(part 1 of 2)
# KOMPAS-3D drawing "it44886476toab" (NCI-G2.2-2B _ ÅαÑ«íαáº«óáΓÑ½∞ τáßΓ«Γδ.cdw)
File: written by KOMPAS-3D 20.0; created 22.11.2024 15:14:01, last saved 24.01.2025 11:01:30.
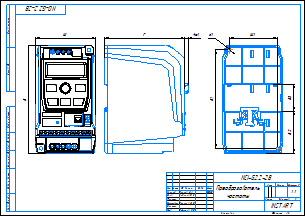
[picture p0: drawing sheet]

Sheet 1: A3, landscape

Document properties: Автор: admin; Полное имя файла: C:\Уралов Работа\Уралов (локальная)\ПЧ\! Китай 3Д-модель NCI\NCI 0.75-2.2 4B\NCI 0.75-2.2 4B.m3d

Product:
- Part/product: it44886476toab
    Масса: 2.32322
  - Body: Тело 17
      Масса: 0.0117014
  - Body: Тело 374
      Масса: 5.48304e-05
  - Body: Тело 265
      Масса: 1.32696e-05
  - Body: Тело 266
      Масса: 1.7366e-05
  - Body: Тело 267
      Масса: 1.7366e-05
  - Body: Тело 103
      Масса: 1.32696e-05
  - Body: Тело 573
      Масса: 4.06595e-05
  - Body: Тело 348
      Масса: 1.32696e-05
  - Body: Тело 270
      Масса: 1.7366e-05
  - Body: Тело 77
      Масса: 1.32696e-05
  - Body: Тело 244
      Масса: 1.65581e-05
  - Body: Тело 536
      Масса: 0.000158536
  - Body: Тело 377
      Масса: 1.65581e-05
  - Body: Тело 272
      Масса: 1.7366e-05
  - Body: Тело 273
      Масса: 5.48304e-05
  - Body: Тело 238
      Масса: 1.7366e-05
  - Body: Тело 274
      Масса: 1.7366e-05
  - Body: Тело 277
      Масса: 1.7366e-05
  - Body: Тело 530
      Масса: 5.61948e-05
  - Body: Тело 278
      Масса: 1.7366e-05
  - Body: Тело 282
      Масса: 1.7366e-05
  - Body: Тело 477
      Масса: 1.51773e-05
  - Body: Тело 526
      Масса: 5.61948e-05
  - Body: Тело 391
      Масса: 1.32696e-05
  - Body: Тело 285
      Масса: 5.48304e-05
  - Body: Тело 287
      Масса: 1.32696e-05
  - Body: Тело 290
      Масса: 0.000413213
  - Body: Тело 269
      Масса: 5.48304e-05
  - Body: Тело 292
      Масса: 1.7366e-05
  - Body: Тело 33
      Масса: 0.00516019
  - Body: Тело 252
      Масса: 5.48304e-05
  - Body: Тело 294
      Масса: 0.000413213
  - Body: Тело 297
      Масса: 3.64631e-05
  - Body: Тело 299
      Масса: 3.64028e-05
  - Body: Тело 283
      Масса: 1.7366e-05
  - Body: Тело 300
      Масса: 1.65581e-05
  - Body: Тело 303
      Масса: 1.65581e-05
  - Body: Тело 516
      Масса: 0.00507377
  - Body: Тело 384
      Масса: 5.48304e-05
  - Body: Тело 360
      Масса: 1.32696e-05
  - Body: Тело 347
      Масса: 1.32696e-05
  - Body: Тело 304
      Масса: 1.65581e-05
  - Body: Тело 307
      Масса: 0.000213463
  - Body: Тело 308
      Масса: 0.000413213
  - Body: Тело 180
      Масса: 1.32696e-05
  - Body: Тело 240
      Масса: 1.7366e-05
  - Body: Тело 309
      Масса: 1.32696e-05
  - Body: Тело 473
      Масса: 0.00425494
  - Body: Тело 311
      Масса: 5.48304e-05
  - Body: Тело 122
      Масса: 1.65581e-05
  - Body: Тело 560
      Масса: 1.65581e-05
  - Body: Тело 312
      Масса: 5.48304e-05
  - Body: Тело 317
      Масса: 1.32696e-05
  - Body: Тело 318
      Масса: 1.32696e-05
  - Body: Тело 321
      Масса: 1.32696e-05
  - Body: Тело 324
      Масса: 1.32696e-05
  - Body: Тело 480
      Масса: 1.51773e-05
  - Body: Тело 288
      Масса: 1.7366e-05
  - Body: Тело 293
      Масса: 5.48304e-05
  - Body: Тело 325
      Масса: 1.32696e-05
  - Body: Тело 99
      Масса: 1.65581e-05
  - Body: Тело 617
      Масса: 1.63919e-05
  - Body: Тело 327
      Масса: 1.32696e-05
  - Body: Тело 31
      Масса: 0.0078835
  - Body: Тело 100
      Масса: 1.65581e-05
  - Body: Тело 105
      Масса: 1.32696e-05
  - Body: Тело 328
      Масса: 1.7366e-05
  - Body: Тело 301
      Масса: 1.65581e-05
  - Body: Тело 331
      Масса: 1.7366e-05
  - Body: Тело 332
      Масса: 1.7366e-05
  - Body: Тело 446
      Масса: 0.000307437
  - Body: Тело 337
      Масса: 1.7366e-05
  - Body: Тело 338
      Масса: 1.7366e-05
  - Body: Тело 570
      Масса: 4.06595e-05
  - Body: Тело 340
      Масса: 1.32696e-05
  - Body: Тело 196
      Масса: 1.32696e-05
  - Body: Тело 357
      Масса: 1.65581e-05
  - Body: Тело 346
      Масса: 1.32696e-05
  - Body: Тело 335
      Масса: 1.32696e-05
  - Body: Тело 281
      Масса: 1.32696e-05
  - Body: Тело 362
      Масса: 1.32696e-05
  - Body: Тело 353
      Масса: 1.7366e-05
  - Body: Тело 355
      Масса: 5.48304e-05
  - Body: Тело 466
      Масса: 0.00829114
  - Body: Тело 358
      Масса: 5.48304e-05
  - Body: Тело 359
      Масса: 1.7366e-05
  - Body: Тело 286
      Масса: 1.7366e-05
  - Body: Тело 86
      Масса: 1.32696e-05
  - Body: Тело 310
      Масса: 1.7366e-05
  - Body: Тело 368
      Масса: 1.32696e-05
  - Body: Тело 370
      Масса: 1.32696e-05
  - Body: Тело 333
      Масса: 1.32696e-05
  - Body: Тело 628
      Масса: 1.51773e-05
  - Body: Тело 371
      Масса: 1.7366e-05
  - Body: Тело 75
      Масса: 1.32696e-05
  - Body: Тело 373
      Масса: 1.32696e-05
  - Body: Тело 375
      Масса: 1.32696e-05
  - Body: Тело 351
      Масса: 2.90876e-05
  - Body: Тело 76
      Масса: 1.65581e-05
  - Body: Тело 259
      Масса: 1.7366e-05
  - Body: Тело 378
      Масса: 0.000413213
  - Body: Тело 95
      Масса: 0.000935996
  - Body: Тело 372
      Масса: 1.7366e-05
  - Body: Тело 322
      Масса: 1.32696e-05
  - Body: Тело 380
      Масса: 1.32696e-05
  - Body: Тело 639
      Масса: 1.63919e-05
  - Body: Тело 385
      Масса: 1.32696e-05
  - Body: Тело 291
      Масса: 0.000213463
  - Body: Тело 386
      Масса: 1.32696e-05
  - Body: Тело 229
      Масса: 1.32696e-05
  - Body: Тело 388
      Масса: 1.32696e-05
  - Body: Тело 389
      Масса: 1.65581e-05
  - Body: Тело 93
      Масса: 3.83377e-05
  - Body: Тело 390
      Масса: 1.65581e-05
  - Body: Тело 143
      Масса: 1.32696e-05
  - Body: Тело 394
      Масса: 1.32696e-05
  - Body: Тело 395
      Масса: 1.32696e-05
  - Body: Тело 354
      Масса: 0.000213463
  - Body: Тело 396
      Масса: 1.7366e-05
  - Body: Тело 397
      Масса: 1.32696e-05
  - Body: Тело 398
      Масса: 1.65581e-05
  - Body: Тело 479
      Масса: 1.51773e-05
  - Body: Тело 402
      Масса: 1.7366e-05
  - Body: Тело 59
      Масса: 1.32696e-05
  - Body: Тело 339
      Масса: 1.32696e-05
  - Body: Тело 404
      Масса: 1.32696e-05
  - Body: Тело 89
      Масса: 0.00142218
  - Body: Тело 406
      Масса: 1.65581e-05
  - Body: Тело 393
      Масса: 1.32696e-05
  - Body: Тело 52
      Масса: 1.32696e-05
  - Body: Тело 407
      Масса: 5.48304e-05
  - Body: Тело 97
      Масса: 0.0015961
  - Body: Тело 410
      Масса: 5.48304e-05
  - Body: Тело 636
      Масса: 1.65581e-05
  - Body: Тело 412
      Масса: 1.7366e-05
  - Body: Тело 413
      Масса: 1.32696e-05
  - Body: Тело 414
      Масса: 1.32696e-05
  - Body: Тело 537
      Масса: 0.000158536
  - Body: Тело 415
      Масса: 1.7366e-05
  - Body: Тело 235
      Масса: 1.7366e-05
  - Body: Тело 419
      Масса: 1.32696e-05
  - Body: Тело 648
      Масса: 0.00426189
  - Body: Тело 420
      Масса: 1.7366e-05
  - Body: Тело 186
      Масса: 1.32696e-05
  - Body: Тело 422
      Масса: 5.48304e-05
  - Body: Тело 381
      Масса: 1.7366e-05
  - Body: Тело 423
      Масса: 1.32696e-05
  - Body: Тело 424
      Масса: 1.7366e-05
  - Body: Тело 98
      Масса: 1.65581e-05
  - Body: Тело 305
      Масса: 1.65581e-05
  - Body: Тело 425
      Масса: 1.32696e-05
  - Body: Тело 365
      Масса: 1.32696e-05
  - Body: Тело 271
      Масса: 1.32696e-05
  - Body: Тело 206
      Масса: 1.32696e-05
  - Body: Тело 429
      Масса: 0.146258
  - Body: Тело 334
      Масса: 1.7366e-05
  - Body: Тело 430
      Масса: 0.146258
  - Body: Тело 350
      Масса: 1.7366e-05
  - Body: Тело 345
      Масса: 1.32696e-05
  - Body: Тело 431
      Масса: 0.146258
  - Body: Тело 364
      Масса: 1.32696e-05
  - Body: Тело 329
      Масса: 1.32696e-05
  - Body: Тело 434
      Масса: 0.000355433
  - Body: Тело 5
      Масса: 0.000355433
  - Body: Тело 124
      Масса: 1.65581e-05
  - Body: Тело 344
      Масса: 1.32696e-05
  - Body: Тело 436
      Масса: 0.000355433
  - Body: Тело 439
      Масса: 0.00113358
  - Body: Тело 606
      Масса: 0.000137594
  - Body: Тело 323
      Масса: 1.32696e-05
  - Body: Тело 441
      Масса: 0.00113358
  - Body: Тело 442
      Масса: 0.000355433
  - Body: Тело 554
      Масса: 4.06595e-05
  - Body: Тело 444
      Масса: 0.000355433
  - Body: Тело 246
      Масса: 1.65581e-05
  - Body: Тело 445
      Масса: 0.00113358
  - Body: Тело 438
      Масса: 0.000355433
  - Body: Тело 106
      Масса: 1.32696e-05
  - Body: Тело 508
      Масса: 1.51773e-05
  - Body: Тело 577
      Масса: 1.7366e-05
  - Body: Тело 392
      Масса: 1.32696e-05
  - Body: Тело 193
      Масса: 1.32696e-05
  - Body: Тело 448
      Масса: 0.000307437
  - Body: Тело 481
      Масса: 1.51773e-05
  - Body: Тело 450
      Масса: 6.34685e-05
  - Body: Тело 222
      Масса: 1.32696e-05
  - Body: Тело 315
      Масса: 1.7366e-05
  - Body: Тело 452
      Масса: 1.63919e-05
  - Body: Тело 53
      Масса: 1.32696e-05
  - Body: Тело 401
      Масса: 1.32696e-05
  - Body: Тело 418
      Масса: 1.7366e-05
  - Body: Тело 517
      Масса: 0.00106884
  - Body: Тело 417
      Масса: 1.32696e-05
  - Body: Тело 453
      Масса: 1.63919e-05
  - Body: Тело 454
      Масса: 0.000382752
  - Body: Тело 428
      Масса: 0.146258
  - Body: Тело 455
      Масса: 1.51773e-05
  - Body: Тело 539
      Масса: 1.51773e-05
  - Body: Тело 457
      Масса: 1.51773e-05
  - Body: Тело 459
      Масса: 3.90329e-05
  - Body: Тело 557
      Масса: 0.00166679
  - Body: Тело 569
      Масса: 1.32696e-05
  - Body: Тело 578
      Масса: 1.32696e-05
  - Body: Тело 626
      Масса: 1.32696e-05
  - Body: Тело 134
      Масса: 1.32696e-05
  - Body: Тело 582
      Масса: 1.65581e-05
  - Body: Тело 203
      Масса: 1.32696e-05
  - Body: Тело 572
      Масса: 1.32696e-05
  - Body: Тело 567
      Масса: 1.32696e-05
  - Body: Тело 207
      Масса: 1.32696e-05
  - Body: Тело 645
      Масса: 1.32696e-05
  - Body: Тело 559
      Масса: 1.65581e-05
  - Body: Тело 152
      Масса: 1.32696e-05
  - Body: Тело 449
      Масса: 0.0658364
  - Body: Тело 316
      Масса: 1.32696e-05
  - Body: Тело 376
      Масса: 1.32696e-05
  - Body: Тело 575
      Масса: 1.32696e-05
  - Body: Тело 576
      Масса: 1.32696e-05
  - Body: Тело 85
      Масса: 1.32696e-05
  - Body: Тело 574
      Масса: 4.06595e-05
  - Body: Тело 399
      Масса: 1.32696e-05
  - Body: Тело 320
      Масса: 1.32696e-05
  - Body: Тело 275
      Масса: 1.7366e-05
  - Body: Тело 213
      Масса: 1.32696e-05
  - Body: Тело 625
      Масса: 1.32696e-05
  - Body: Тело 644
      Масса: 0.000158536
  - Body: Тело 584
      Масса: 4.06595e-05
  - Body: Тело 70
      Масса: 1.65581e-05
  - Body: Тело 588
      Масса: 1.32696e-05
  - Body: Тело 276
      Масса: 1.7366e-05
  - Body: Тело 363
      Масса: 1.32696e-05
  - Body: Тело 474
      Масса: 1.51773e-05
  - Body: Тело 548
      Масса: 2.98222e-05
  - Body: Тело 409
      Масса: 5.48304e-05
  - Body: Тело 472
      Масса: 0.00329327
  - Body: Тело 533
      Масса: 5.61948e-05
  - Body: Тело 647
      Масса: 0.00426189
  - Body: Тело 586
      Масса: 1.32696e-05
  - Body: Тело 262
      Масса: 1.7366e-05
  - Body: Тело 562
      Масса: 0.000382752
  - Body: Тело 379
      Масса: 1.32696e-05
  - Body: Тело 632
      Масса: 1.51773e-05
  - Body: Тело 565
      Масса: 4.06595e-05
  - Body: Тело 118
      Масса: 0.000413213
  - Body: Тело 597
      Масса: 7.12116e-06
  - Body: Тело 613
      Масса: 1.63919e-05
  - Body: Тело 387
      Масса: 1.32696e-05
  - Body: Тело 593
      Масса: 1.32696e-05
  - Body: Тело 408
      Масса: 5.48304e-05
  - Body: Тело 109
      Масса: 1.32696e-05
  - Body: Тело 163
      Масса: 1.32696e-05
  - Body: Тело 488
      Масса: 1.51773e-05
  - Body: Тело 367
      Масса: 1.32696e-05
  - Body: Тело 411
      Масса: 5.48304e-05
  - Body: Тело 583
      Масса: 4.06595e-05
  - Body: Тело 598
      Масса: 7.12116e-06
  - Body: Тело 551
      Масса: 0.000255388
  - Body: Тело 405
      Масса: 1.32696e-05
  - Body: Тело 619
      Масса: 1.32696e-05
  - Body: Тело 361
      Масса: 1.32696e-05
  - Body: Тело 589
      Масса: 1.32696e-05
  - Body: Тело 499
      Масса: 1.51773e-05
  - Body: Тело 440
      Масса: 0.000355433
  - Body: Тело 640
      Масса: 1.63919e-05
  - Body: Тело 150
      Масса: 1.32696e-05
  - Body: Тело 568
      Масса: 1.32696e-05
  - Body: Тело 194
      Масса: 1.32696e-05
  - Body: Тело 251
      Масса: 1.7366e-05
  - Body: Тело 342
      Масса: 0.00166679
  - Body: Тело 604
      Масса: 5.61948e-05
  - Body: Тело 650
      Масса: 0.00426189
  - Body: Тело 161
      Масса: 1.32696e-05
  - Body: Тело 611
      Масса: 0.000158536
  - Body: Тело 210
      Масса: 1.32696e-05
  - Body: Тело 540
      Масса: 1.51773e-05
  - Body: Тело 296
      Масса: 3.6965e-05
  - Body: Тело 601
      Масса: 5.61948e-05
  - Body: Тело 484
      Масса: 0.000158536
  - Body: Тело 622
      Масса: 1.32696e-05
  - Body: Тело 527
      Масса: 0.000141095
  - Body: Тело 624
      Масса: 1.32696e-05
  - Body: Тело 121
      Масса: 0.000413213
  - Body: Тело 600
      Масса: 5.61948e-05
  - Body: Тело 603
      Масса: 5.61948e-05
  - Body: Тело 607
      Масса: 1.32696e-05
  - Body: Тело 289
      Масса: 1.7366e-05
  - Body: Тело 471
      Масса: 0.00329327
  - Body: Тело 313
      Масса: 1.7366e-05
  - Body: Тело 591
      Масса: 7.12116e-06
  - Body: Тело 356
      Масса: 1.65581e-05
  - Body: Тело 306
      Масса: 1.65581e-05
  - Body: Тело 541
      Масса: 0.000158536
  - Body: Тело 511
      Масса: 1.51773e-05
  - Body: Тело 160
      Масса: 1.32696e-05
  - Body: Тело 566
      Масса: 1.32696e-05
  - Body: Тело 563
      Масса: 4.06595e-05
  - Body: Тело 638
      Масса: 1.7366e-05
  - Body: Тело 489
      Масса: 1.51773e-05
  - Body: Тело 456
      Масса: 1.51773e-05
  - Body: Тело 485
      Масса: 0.000158536
  - Body: Тело 284
      Масса: 1.7366e-05
  - Body: Тело 138
      Масса: 2.23009e-05
  - Body: Тело 225
      Масса: 1.32696e-05
  - Body: Тело 546
      Масса: 0.000255388
  - Body: Тело 113
      Масса: 0.000413213
  - Body: Тело 642
      Масса: 3.90329e-05
  - Body: Тело 618
      Масса: 1.63919e-05
  - Body: Тело 525
      Масса: 0.000213463
  - Body: Тело 164
      Масса: 1.32696e-05
  - Body: Тело 253
      Масса: 1.7366e-05
  - Body: Тело 561
      Масса: 1.65581e-05
  - Body: Тело 594
      Масса: 1.32696e-05
  - Body: Тело 482
      Масса: 1.51773e-05
  - Body: Тело 81
      Масса: 1.32696e-05
  - Body: Тело 280
      Масса: 1.32696e-05
  - Body: Тело 494
      Масса: 1.51773e-05
  - Body: Тело 641
      Масса: 3.90329e-05
  - Body: Тело 564
      Масса: 4.06595e-05
  - Body: Тело 633
      Масса: 1.51773e-05
  - Body: Тело 518
      Масса: 0.00166679
  - Body: Тело 620
      Масса: 1.7366e-05
  - Body: Тело 497
      Масса: 1.51773e-05
  - Body: Тело 151
      Масса: 1.65581e-05
  - Body: Тело 302
      Масса: 1.65581e-05
  - Body: Тело 110
      Масса: 1.32696e-05
  - Body: Тело 646
      Масса: 0.000137594
  - Body: Тело 264
      Масса: 1.7366e-05
  - Body: Тело 635
      Масса: 1.65581e-05
  - Body: Тело 608
      Масса: 0.00166679
  - Body: Тело 460
      Масса: 3.90329e-05
  - Body: Тело 403
      Масса: 1.7366e-05
  - Body: Тело 612
      Масса: 0.000158536
  - Body: Тело 492
      Масса: 1.51773e-05
  - Body: Тело 139
      Масса: 0.000194606
  - Body: Тело 400
      Масса: 1.7366e-05
  - Body: Тело 605
      Масса: 5.61948e-05
  - Body: Тело 623
      Масса: 1.32696e-05
  - Body: Тело 117
      Масса: 0.000413213
  - Body: Тело 185
      Масса: 1.32696e-05
  - Body: Тело 631
      Масса: 1.51773e-05
  - Body: Тело 580
      Масса: 1.32696e-05
  - Body: Тело 349
      Масса: 1.7366e-05
  - Body: Тело 621
      Масса: 1.32696e-05
  - Body: Тело 627
      Масса: 0.000255388
  - Body: Тело 531
      Масса: 5.61948e-05
  - Body: Тело 649
      Масса: 0.00426189
  - Body: Тело 585
      Масса: 4.06595e-05
  - Body: Тело 236
      Масса: 1.7366e-05
  - Body: Тело 513
      Масса: 1.51773e-05
  - Body: Тело 426
      Масса: 1.32696e-05
  - Body: Тело 341
      Масса: 0.00166679
  - Body: Тело 470
      Масса: 0.00329329
  - Body: Тело 382
      Масса: 5.48304e-05
  - Body: Тело 227
      Масса: 1.32696e-05
  - Body: Тело 476
      Масса: 1.51773e-05
  - Body: Тело 538
      Масса: 1.51773e-05
  - Body: Тело 596
      Масса: 1.32696e-05
  - Body: Тело 609
      Масса: 1.7366e-05
  - Body: Тело 610
      Масса: 0.00166679
  - Body: Тело 263
      Масса: 1.7366e-05
  - Body: Тело 629
      Масса: 1.51773e-05
  - Body: Тело 336
      Масса: 3.64028e-05
  - Body: Тело 495
      Масса: 1.51773e-05
  - Body: Тело 168
      Масса: 1.32696e-05
  - Body: Тело 298
      Масса: 3.64495e-05
  - Body: Тело 279
      Масса: 1.32696e-05
  - Body: Тело 72
      Масса: 1.65581e-05
  - Body: Тело 500
      Масса: 1.51773e-05
  - Body: Тело 505
      Масса: 1.51773e-05
  - Body: Тело 558
      Масса: 0.00726683
  - Body: Тело 630
      Масса: 1.51773e-05
  - Body: Тело 602
      Масса: 5.61948e-05
  - Body: Тело 556
      Масса: 0.00166679
  - Body: Тело 555
      Масса: 0.00166679
  - Body: Тело 634
      Масса: 1.51773e-05
  - Body: Тело 435
      Масса: 0.00113358
  - Body: Тело 416
      Масса: 1.7366e-05
  - Body: Тело 190
      Масса: 1.32696e-05
  - Body: Тело 330
      Масса: 1.7366e-05
  - Body: Тело 28
      Масса: 0.00135688
  - Body: Тело 553
      Масса: 4.06595e-05
  - Body: Тело 176
      Масса: 1.32696e-05
  - Body: Тело 552
      Масса: 4.06595e-05
  - Body: Тело 534
      Масса: 1.32696e-05
  - Body: Тело 595
      Масса: 1.32696e-05
  - Body: Тело 23
      Масса: 0.0243258
  - Body: Тело 247
      Масса: 1.7366e-05
  - Body: Тело 314
      Масса: 1.7366e-05
  - Body: Тело 126
      Масса: 0.000512664
  - Body: Тело 157
      Масса: 1.32696e-05
  - Body: Тело 550
      Масса: 0.000255388
  - Body: Тело 32
      Масса: 0.0135217
  - Body: Тело 592
      Масса: 7.12116e-06
  - Body: Тело 366
      Масса: 1.7366e-05
  - Body: Тело 504
      Масса: 1.51773e-05
  - Body: Тело 258
      Масса: 1.7366e-05
  - Body: Тело 421
      Масса: 1.7366e-05
  - Body: Тело 35
      Масса: 0.262997
  - Body: Тело 204
      Масса: 1.32696e-05
  - Body: Тело 549
      Масса: 0.000255388
  - Body: Тело 257
      Масса: 1.7366e-05
  - Body: Тело 614
      Масса: 1.63919e-05
  - Body: Тело 547
      Масса: 0.000255388
  - Body: Тело 41
      Масса: 0.0119524
  - Body: Тело 71
      Масса: 1.65581e-05
  - Body: Тело 506
      Масса: 1.51773e-05
  - Body: Тело 545
      Масса: 1.51773e-05
  - Body: Тело 145
      Масса: 1.32696e-05
  - Body: Тело 461
      Масса: 0.000404362
  - Body: Тело 502
      Масса: 1.51773e-05
  - Body: Тело 352
      Масса: 2.90876e-05
  - Body: Тело 120
      Масса: 0.000413213
  - Body: Тело 295
      Масса: 1.65581e-05
  - Body: Тело 544
      Масса: 0.000158536
  - Body: Тело 469
      Масса: 0.0113891
  - Body: Тело 146
      Масса: 1.32696e-05
  - Body: Тело 149
      Масса: 1.32696e-05
  - Body: Тело 615
      Масса: 1.63919e-05
  - Body: Тело 543
      Масса: 0.000158536
  - Body: Тело 542
      Масса: 0.000158536
  - Body: Тело 462
      Масса: 0.000404362
  - Body: Тело 616
      Масса: 1.63919e-05
  - Body: Тело 343
      Масса: 0.00166679
  - Body: Тело 532
      Масса: 5.61948e-05
  - Body: Тело 493
      Масса: 1.51773e-05
  - Body: Тело 529
      Масса: 5.61948e-05
  - Body: Тело 579
      Масса: 0.00017125
  - Body: Тело 200
      Масса: 1.32696e-05
  - Body: Тело 239
      Масса: 5.48304e-05
  - Body: Тело 443
      Масса: 0.00113358
  - Body: Тело 216
      Масса: 0.000280294
  - Body: Тело 468
      Масса: 0.0253857
  - Body: Тело 64
      Масса: 1.65581e-05
  - Body: Тело 528
      Масса: 0.000141095
  - Body: Тело 599
      Масса: 7.12116e-06
  - Body: Тело 590
      Масса: 1.32696e-05
  - Body: Тело 191
      Масса: 1.32696e-05
  - Body: Тело 523
      Масса: 0.000255388
  - Body: Тело 458
      Масса: 1.51773e-05
  - Body: Тело 319
      Масса: 1.32696e-05
  - Body: Тело 49
      Масса: 0.00944
  - Body: Тело 522
      Масса: 1.65581e-05
  - Body: Тело 521
      Масса: 1.32696e-05
  - Body: Тело 571
      Масса: 0.00166679
  - Body: Тело 509
      Масса: 1.51773e-05
  - Body: Тело 326
      Масса: 1.32696e-05
  - Body: Тело 520
      Масса: 5.48304e-05
  - Body: Тело 427
      Масса: 1.32696e-05
  - Body: Тело 519
      Масса: 1.7366e-05
  - Body: Тело 637
      Масса: 1.51773e-05
  - Body: Тело 524
      Масса: 1.65581e-05
  - Body: Тело 432
      Масса: 0.000118347
  - Body: Тело 487
      Масса: 1.65581e-05
  - Body: Тело 510
      Масса: 1.51773e-05
  - Body: Тело 515
      Масса: 0.00507372
  - Body: Тело 512
      Масса: 1.51773e-05
  - Body: Тело 155
      Масса: 1.32696e-05
  - Body: Тело 587
      Масса: 1.32696e-05
  - Body: Тело 174
      Масса: 1.65581e-05
  - Body: Тело 507
      Масса: 1.51773e-05
  - Body: Тело 12
      Масса: 0.000703761
  - Body: Тело 187
      Масса: 1.32696e-05
  - Body: Тело 447
      Масса: 0.000307437
  - Body: Тело 503
      Масса: 1.51773e-05
  - Body: Тело 501
      Масса: 1.51773e-05
  - Body: Тело 369
      Масса: 1.32696e-05
  - Body: Тело 60
      Масса: 1.32696e-05
  - Body: Тело 498
      Масса: 1.51773e-05
  - Body: Тело 535
      Масса: 1.52051e-05
  - Body: Тело 437
      Масса: 0.00113358
  - Body: Тело 496
      Масса: 1.51773e-05
  - Body: Тело 433
      Масса: 0.000118347
  - Body: Тело 491
      Масса: 1.65581e-05
  - Body: Тело 490
      Масса: 1.51773e-05
  - Body: Тело 581
      Масса: 1.65581e-05
  - Body: Тело 486
      Масса: 0.000158536
  - Body: Тело 483
      Масса: 1.51773e-05
  - Body: Тело 514
      Масса: 1.51773e-05
  - Body: Тело 643
      Масса: 0.000158536
  - Body: Тело 125
      Масса: 1.65581e-05
  - Body: Тело 383
      Масса: 0.000340816
  - Body: Тело 465
      Масса: 0.00829114
  - Body: Тело 478
      Масса: 1.51773e-05
  - Body: Тело 451
      Масса: 6.34685e-05
  - Body: Тело 475
      Масса: 1.51773e-05
  - Body: Тело 467
      Масса: 0.00436982
  - Body: Тело 268
      Масса: 5.48304e-05
  - Body: Тело 464
      Масса: 0.00829425
  - Body: Тело 226
      Масса: 0.000413213
  - Body: Тело 463
      Масса: 0.000404362
  - Body: Тело 170
      Масса: 1.32696e-05
  - Body: Тело 261
      Масса: 3.83377e-05
  - Body: Тело 260
      Масса: 1.7366e-05
  - Body: Тело 167
      Масса: 1.32696e-05
  - Body: Тело 256
      Масса: 1.7366e-05
  - Body: Тело 119
      Масса: 0.000413213
  - Body: Тело 255
      Масса: 1.7366e-05
  - Body: Тело 254
      Масса: 1.32696e-05
  - Body: Тело 250
      Масса: 1.7366e-05
  - Body: Тело 249
      Масса: 1.7366e-05
  - Body: Тело 248
      Масса: 1.7366e-05
  - Body: Тело 19
      Масса: 0.0117014
  - Body: Тело 114
      Масса: 0.000413213
  - Body: Тело 234
      Масса: 1.7366e-05
  - Body: Тело 245
      Масса: 1.65581e-05
  - Body: Тело 243
      Масса: 1.65581e-05
  - Body: Тело 242
      Масса: 1.65581e-05
  - Body: Тело 65
      Масса: 1.65581e-05
  - Body: Тело 241
      Масса: 0.000424983
  - Body: Тело 141
      Масса: 0.000213463
  - Body: Тело 237
      Масса: 1.7366e-05
  - Body: Тело 1
      Масса: 0.00113358
  - Body: Тело 233
      Масса: 1.7366e-05
  - Body: Тело 232
      Масса: 5.48304e-05
  - Body: Тело 231
      Масса: 0.00398049
  - Body: Тело 230
      Масса: 1.32696e-05
  - Body: Тело 184
      Масса: 1.32696e-05
  - Body: Тело 228
      Масса: 1.32696e-05
  - Body: Тело 224
      Масса: 1.32696e-05
  - Body: Тело 162
      Масса: 1.65581e-05
  - Body: Тело 223
      Масса: 1.32696e-05
  - Body: Тело 221
      Масса: 1.65581e-05
  - Body: Тело 220
      Масса: 1.32696e-05
  - Body: Тело 219
      Масса: 1.32696e-05
  - Body: Тело 218
      Масса: 1.32696e-05
  - Body: Тело 217
      Масса: 1.32696e-05
  - Body: Тело 215
      Масса: 1.65581e-05
  - Body: Тело 9
      Масса: 0.000703761
  - Body: Тело 214
      Масса: 1.32696e-05
  - Body: Тело 212
      Масса: 1.32696e-05
  - Body: Тело 211
      Масса: 1.32696e-05
  - Body: Тело 209
      Масса: 1.32696e-05
  - Body: Тело 208
      Масса: 1.7366e-05
  - Body: Тело 205
      Масса: 1.32696e-05
  - Body: Тело 202
      Масса: 1.32696e-05
  - Body: Тело 201
      Масса: 1.32696e-05
  - Body: Тело 29
      Масса: 0.00135688
  - Body: Тело 199
      Масса: 1.32696e-05
  - Body: Тело 198
      Масса: 1.32696e-05
  - Body: Тело 197
      Масса: 1.32696e-05
  - Body: Тело 195
      Масса: 1.32696e-05
  - Body: Тело 192
      Масса: 1.32696e-05
  - Body: Тело 189
      Масса: 1.32696e-05
  - Body: Тело 188
      Масса: 1.32696e-05
  - Body: Тело 183
      Масса: 1.32696e-05
  - Body: Тело 182
      Масса: 1.32696e-05
  - Body: Тело 181
      Масса: 1.32696e-05
  - Body: Тело 179
      Масса: 1.32696e-05
  - Body: Тело 178
      Масса: 1.32696e-05
  - Body: Тело 44
      Масса: 0.0119524
  - Body: Тело 50
      Масса: 0.00101975
  - Body: Тело 177
      Масса: 1.32696e-05
  - Body: Тело 175
      Масса: 1.32696e-05
  - Body: Тело 45
      Масса: 0.0267013
  - Body: Тело 137
      Масса: 1.32696e-05
  - Body: Тело 173
      Масса: 1.32696e-05
  - Body: Тело 172
      Масса: 1.65581e-05
  - Body: Тело 153
      Масса: 1.32696e-05
  - Body: Тело 171
      Масса: 1.32696e-05
  - Body: Тело 169
      Масса: 1.32696e-05
  - Body: Тело 140
      Масса: 0.000213463
  - Body: Тело 166
      Масса: 1.32696e-05
  - Body: Тело 165
      Масса: 1.65581e-05
  - Body: Тело 159
      Масса: 1.32696e-05
  - Body: Тело 116
      Масса: 0.000413213
  - Body: Тело 158
      Масса: 1.32696e-05
  - Body: Тело 156
      Масса: 1.32696e-05
  - Body: Тело 154
      Масса: 1.32696e-05
  - Body: Тело 148
      Масса: 1.32696e-05
  - Body: Тело 147
      Масса: 1.32696e-05
  - Body: Тело 24
      Масса: 0.0110484
  - Body: Тело 62
      Масса: 1.32696e-05
  - Body: Тело 144
      Масса: 1.32696e-05
  - Body: Тело 142
      Масса: 0.000213463
  - Body: Тело 136
      Масса: 1.32696e-05
  - Body: Тело 135
      Масса: 1.32696e-05
  - Body: Тело 38
      Масса: 0.00631989
  - Body: Тело 133
      Масса: 1.32696e-05
  - Body: Тело 132
      Масса: 1.32696e-05
  - Body: Тело 131
      Масса: 1.32696e-05
  - Body: Тело 16
      Масса: 0.000703761
  - Body: Тело 130
      Масса: 1.32696e-05
  - Body: Тело 112
      Масса: 0.000413213
  - Body: Тело 129
      Масса: 1.32696e-05
  - Body: Тело 128
      Масса: 1.32696e-05
  - Body: Тело 127
      Масса: 1.32696e-05
  - Body: Тело 123
      Масса: 1.65581e-05
  - Body: Тело 115
      Масса: 0.000413213
  - Body: Тело 111
      Масса: 0.000194606
  - Body: Тело 108
      Масса: 1.32696e-05
  - Body: Тело 107
      Масса: 1.32696e-05
  - Body: Тело 104
      Масса: 1.32696e-05
  - Body: Тело 102
      Масса: 1.32696e-05
  - Body: Тело 90
      Масса: 0.000966482
  - Body: Тело 101
      Масса: 1.32696e-05
  - Body: Тело 96
      Масса: 0.00181049
  - Body: Тело 94
      Масса: 0.00554276
  - Body: Тело 92
      Масса: 3.83377e-05
  - Body: Тело 91
      Масса: 0.0246688
  - Body: Тело 15
      Масса: 0.000703761
  - Body: Тело 88
      Масса: 0.000873873
  - Body: Тело 87
      Масса: 0.000966482
  - Body: Тело 84
      Масса: 1.32696e-05
  - Body: Тело 83
      Масса: 1.32696e-05
  - Body: Тело 82
      Масса: 1.32696e-05
  - Body: Тело 80
      Масса: 1.32696e-05
  - Body: Тело 79
      Масса: 1.32696e-05
  - Body: Тело 78
      Масса: 1.65581e-05
  - Body: Тело 74
      Масса: 1.65581e-05
  - Body: Тело 48
      Масса: 0.00853877
  - Body: Тело 73
      Масса: 1.65581e-05
  - Body: Тело 69
      Масса: 1.65581e-05
  - Body: Тело 68
      Масса: 1.65581e-05
  - Body: Тело 67
      Масса: 1.65581e-05
  - Body: Тело 66
      Масса: 1.65581e-05
  - Body: Тело 63
      Масса: 1.65581e-05
  - Body: Тело 57
      Масса: 1.32696e-05
  - Body: Тело 61
      Масса: 1.32696e-05
  - Body: Тело 58
      Масса: 1.32696e-05
  - Body: Тело 56
      Масса: 1.32696e-05
  - Body: Тело 55
      Масса: 1.32696e-05
  - Body: Тело 54
      Масса: 1.32696e-05
  - Body: Тело 51
      Масса: 1.32696e-05
  - Body: Тело 47
      Масса: 0.551587
  - Body: Тело 46
      Масса: 0.0119034
  - Body: Тело 43
      Масса: 0.0119524
  - Body: Тело 42
      Масса: 0.0119524
  - Body: Тело 40
      Масса: 0.0119524
  - Body: Тело 39
      Масса: 0.0119524
  - Body: Тело 37
      Масса: 0.0343584
  - Body: Тело 36
      Масса: 0.0668131
  - Body: Тело 34
      Масса: 0.00831628
  - Body: Тело 30
      Масса: 0.000935996
  - Body: Тело 27
      Масса: 0.00135688
  - Body: Тело 26
      Масса: 0.00135688
  - Body: Тело 25
      Масса: 0.00135688
  - Body: Тело 22
      Масса: 0.0636504
  - Body: Тело 21
      Масса: 0.0864411
  - Body: Тело 20
      Масса: 0.120334
  - Body: Тело 18
      Масса: 0.0117014
  - Body: Тело 14
      Масса: 0.000703761
  - Body: Тело 13
      Масса: 0.000703761
  - Body: Тело 11
      Масса: 0.000703761
  - Body: Тело 10
      Масса: 0.0160396
  - Body: Тело 8
      Масса: 0.000703761
  - Body: Тело 7
      Масса: 0.000703761
  - Body: Тело 6
      Масса: 0.000355433
  - Body: Тело 4
      Масса: 0.000355433
  - Body: Тело 3
      Масса: 0.00113358
  - Body: Тело 2
      Масса: 0.00113358

Title block, sheet 1: Наименование: Преобразователь / частоты; designation: NCI-G2.2-2B; Количество листов документа: 1; organisation: INSTART; cell 10: Согласовано; Форматы листов документа: A3; stored path: P:\INSTART\Технический отдел\ОР\Прочие задачи\КД на номенклатурный ряд\КД на типоразмеры ПЧ\NCI\NCI-G0.75_P1.5-4B\NCI-G0.75_P1.5-4B _ Преобразователь частоты.cdw; Разработал: Уралов Д.А.; Проверил: Андреев Н.В.; Подписал: Смелков Ж.Е.; Утвердил: Ефремов И.Н.; Разработал, date: 13.01.25

Views: Вид 1
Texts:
  Кривая без истории:10000
  Кривая без истории:10001
  Кривая без истории:10002
  Кривая без истории:10003
  Кривая без истории:10004
  Кривая без истории:10005
  Кривая без истории:10006
  Кривая без истории:10007
  Кривая без истории:10008
  Кривая без истории:10009
  Кривая без истории:10010
  Кривая без истории:10011
  Кривая без истории:10012
  Кривая без истории:10013
  Кривая без истории:10014
  Кривая без истории:10015
  Кривая без истории:10016
  Кривая без истории:10017
  Кривая без истории:10018
  Кривая без истории:10019
  Кривая без истории:10020
  Кривая без истории:10021
  Кривая без истории:10022
  Кривая без истории:10023
  Кривая без истории:10024
  Кривая без истории:10025
  Кривая без истории:10026
  Кривая без истории:10027
  Кривая без истории:10028
  Кривая без истории:10029
  Кривая без истории:10030
  Кривая без истории:10031
  Кривая без истории:10032
  Кривая без истории:10033
  Кривая без истории:10034
  Кривая без истории:10035
  Кривая без истории:10036
  Кривая без истории:10037
  Кривая без истории:10038
  Кривая без истории:10039
  Кривая без истории:10040
  Кривая без истории:10041
  Кривая без истории:10042
  Кривая без истории:10043
  Кривая без истории:10044
  Кривая без истории:10045
  Кривая без истории:10046
  Кривая без истории:10047
  Кривая без истории:10048
  Кривая без истории:10049
  Кривая без истории:10050
  Кривая без истории:10051
  Кривая без истории:10052
  Кривая без истории:10053
  Кривая без истории:10054
  Кривая без истории:10055
  Кривая без истории:10056
  Кривая без истории:10057
  Кривая без истории:10058
  Кривая без истории:10059
  Кривая без истории:10060
  Кривая без истории:10061
  Кривая без истории:10062
  Кривая без истории:10063
  Кривая без истории:10064
  Кривая без истории:10065
  Кривая без истории:10066
  Кривая без истории:10067
  Кривая без истории:10068
  Кривая без истории:10069
  Кривая без истории:10070
  Кривая без истории:10071
  Кривая без истории:10072
  Кривая без истории:10073
  Кривая без истории:10074
  Кривая без истории:10075
  Кривая без истории:10076
  Кривая без истории:10077
  Кривая без истории:10078
  Кривая без истории:10079
  Кривая без истории:10080
  Кривая без истории:10081
  Кривая без истории:10082
  Кривая без истории:10083
  Кривая без истории:10084
  Кривая без истории:10085
  Кривая без истории:10086
  Кривая без истории:10087
  Кривая без истории:10088
  Кривая без истории:10089
  Кривая без истории:10090
  Кривая без истории:10091
  Кривая без истории:10092
  Кривая без истории:10093
  Кривая без истории:10094
  Кривая без истории:10095
  Кривая без истории:10096
  Кривая без истории:10097
  Кривая без истории:10098
  Кривая без истории:10099
  Кривая без истории:10100
  Кривая без истории:10101
  Кривая без истории:10102
  Кривая без истории:10103
  Кривая без истории:10104
  Кривая без истории:10105
  Кривая без истории:10106
  Кривая без истории:10107
  Кривая без истории:10108
  Кривая без истории:10109
  Кривая без истории:10110
  Кривая без истории:10111
  Кривая без истории:10112
  Кривая без истории:10113
  Кривая без истории:10114
  Кривая без истории:10115
  Кривая без истории:10116
  Кривая без истории:10117
  Кривая без истории:10118
  Кривая без истории:10119
  Кривая без истории:10120
  Кривая без истории:10121
  Кривая без истории:10122
  Кривая без истории:10123
  Кривая без истории:10124
  Кривая без истории:10125
  Кривая без истории:10126
  Кривая без истории:10127
  Кривая без истории:10128
  Кривая без истории:10129
  Кривая без истории:10130
  Кривая без истории:10131
  Кривая без истории:10132
  Кривая без истории:10133
  Кривая без истории:10134
  Кривая без истории:10135
  Кривая без истории:10136
  Кривая без истории:10137
  Кривая без истории:10138
  Кривая без истории:10139
  Кривая без истории:10140
  Кривая без истории:10141
  Кривая без истории:10142
  Кривая без истории:10143
  Кривая без истории:10144
  Кривая без истории:10145
  Кривая без истории:10146
  Кривая без истории:10147
  Кривая без истории:10148
  Кривая без истории:10149
  Кривая без истории:10150
  Кривая без истории:10151
  Кривая без истории:10152
  Кривая без истории:10153
  Кривая без истории:10154
  Кривая без истории:10155
  Кривая без истории:10156
  Кривая без истории:10157
  Кривая без истории:10158
  Кривая без истории:10159
  Кривая без истории:10160
  Кривая без истории:10161
  Кривая без истории:10162
  Кривая без истории:10163
  Кривая без истории:10164
  Кривая без истории:10165
  Кривая без истории:10166
  Кривая без истории:10167
  Кривая без истории:10168
  Кривая без истории:10169
  Кривая без истории:10170
  Кривая без истории:10171
  Кривая без истории:10172
  Кривая без истории:10173
  Кривая без истории:10174
  Кривая без истории:10175
  Кривая без истории:10176
  Кривая без истории:10177
  Кривая без истории:10178
  Кривая без истории:10179
  Кривая без истории:10180
  Кривая без истории:10181
  Кривая без истории:10182
  Кривая без истории:10183
  Кривая без истории:10184
  Кривая без истории:10185
  Кривая без истории:10186
  Кривая без истории:10187
  Кривая без истории:10188
  Кривая без истории:10189
  Кривая без истории:10190
  Кривая без истории:10191
  Кривая без истории:10192
  Кривая без истории:10193
  Кривая без истории:10194
  Кривая без истории:10195
  Кривая без истории:10196
  Кривая без истории:10197
  Кривая без истории:10198
  Кривая без истории:10199
  Кривая без истории:10200
  Кривая без истории:10201
  Кривая без истории:10202
  Кривая без истории:10203
  Кривая без истории:10204
  Кривая без истории:10205
  Кривая без истории:10206
  Кривая без истории:10207
  Кривая без истории:10208
  Кривая без истории:10209
  Кривая без истории:10210
  Кривая без истории:10211
  Кривая без истории:10212
  Кривая без истории:10213
  Кривая без истории:10214
  Кривая без истории:10215
  Кривая без истории:10216
  Кривая без истории:10217
  Кривая без истории:10218
  Кривая без истории:10219
  Кривая без истории:10220
  Кривая без истории:10221
  Кривая без истории:10222
  Кривая без истории:10223
  Кривая без истории:10224
  Кривая без истории:10225
  Кривая без истории:10226
  Кривая без истории:10227
  Кривая без истории:10228
  Кривая без истории:10229
  Кривая без истории:10230
  Кривая без истории:10231
  Кривая без истории:10232
  Кривая без истории:10233
  Кривая без истории:10234
  Кривая без истории:10235
  Кривая без истории:10236
  Кривая без истории:10237
  Кривая без истории:10238
  Кривая без истории:10239
  Кривая без истории:10240
  Кривая без истории:10241
  Кривая без истории:10242
  Кривая без истории:10243
  Кривая без истории:10244
  Кривая без истории:10245
  Кривая без истории:10246
  Кривая без истории:10247
  Кривая без истории:10248
  Кривая без истории:10249
  Кривая без истории:10250
  Кривая без истории:10251
  Кривая без истории:10252
  Кривая без истории:10253
  Кривая без истории:10254
  Кривая без истории:10255
  Кривая без истории:10256
  Кривая без истории:10257
  Кривая без истории:10258
  Кривая без истории:10259
  Кривая без истории:10260
  Кривая без истории:10261
  Кривая без истории:10262
  Кривая без истории:10263
  Кривая без истории:10264
  Кривая без истории:10265
  Кривая без истории:10266
  Кривая без истории:10267
  Кривая без истории:10268
  Кривая без истории:10269
  Кривая без истории:10270
  Кривая без истории:10271
  Кривая без истории:10272
  Кривая без истории:10273
  Кривая без истории:10274
  Кривая без истории:10275
  Кривая без истории:10276
  Кривая без истории:10277
  Кривая без истории:10278
  Кривая без истории:10279
  Кривая без истории:10280
  Кривая без истории:10281
  Кривая без истории:10282
  Кривая без истории:10283
  Кривая без истории:10284
  Кривая без истории:10285
  Кривая без истории:10286
  Кривая без истории:10287
  Кривая без истории:10288
  Кривая без истории:10289
  Кривая без истории:10290
  Кривая без истории:10291
  Кривая без истории:10292
  Кривая без истории:10293
  Кривая без истории:10294
  Кривая без истории:10295
  Кривая без истории:10296
  Кривая без истории:10297
  Кривая без истории:10298
  Кривая без истории:10299
  Кривая без истории:10300
  Кривая без истории:10301
  Кривая без истории:10302
  Кривая без истории:10303
  Кривая без истории:10304
  Кривая без истории:10305
  Кривая без истории:10306
  Кривая без истории:10307
  Кривая без истории:10308
  Кривая без истории:10309
  Кривая без истории:10310
  Кривая без истории:10311
  Кривая без истории:10312
  Кривая без истории:10313
  Кривая без истории:10314
  Кривая без истории:10315
  Кривая без истории:10316
  Кривая без истории:10317
  Кривая без истории:10318
  Кривая без истории:10319
  Кривая без истории:10320
  Кривая без истории:10321
  Кривая без истории:10322
  Кривая без истории:10323
  Кривая без истории:10324
  Кривая без истории:10325
  Кривая без истории:10326
  Кривая без истории:10327
  Кривая без истории:10328
  Кривая без истории:10329
  Кривая без истории:10330
  Кривая без истории:10331
  Кривая без истории:10332
  Кривая без истории:10333
  Кривая без истории:10334
  Кривая без истории:10335
  Кривая без истории:10336
  Кривая без истории:10337
  Кривая без истории:10338
  Кривая без истории:10339
  Кривая без истории:10340
  Кривая без истории:10341
  Кривая без истории:10342
  Кривая без истории:10343
  Кривая без истории:10344
  Кривая без истории:10345
  Кривая без истории:10346
  Кривая без истории:10347
  Кривая без истории:10348
  Кривая без истории:10349
  Кривая без истории:10350
  Кривая без истории:10351
  Кривая без истории:10352
  Кривая без истории:10353
  Кривая без истории:10354
  Кривая без истории:10355
  Кривая без истории:10356
  Кривая без истории:10357
  Кривая без истории:10358
  Кривая без истории:10359
  Кривая без истории:10360
  Кривая без истории:10361
  Кривая без истории:10362
  Кривая без истории:10363
  Кривая без истории:10364
  Кривая без истории:10365
  Кривая без истории:10366
  Кривая без истории:10367
  Кривая без истории:10368
  Кривая без истории:10369
  Кривая без истории:10370
  Кривая без истории:10371
  Кривая без истории:10372
  Кривая без истории:10373
  Кривая без истории:10374
  Кривая без истории:10375
  Кривая без истории:10376
  Кривая без истории:10377
  Кривая без истории:10378
  Кривая без истории:10379
  Кривая без истории:10380
  Кривая без истории:10381
  Кривая без истории:10382
  Кривая без истории:10383
  Кривая без истории:10384
  Кривая без истории:10385
  Кривая без истории:10386
  Кривая без истории:10387
  Кривая без истории:10388
  Кривая без истории:10389
  Кривая без истории:10390
  Кривая без истории:10391
  Кривая без истории:10392
  Кривая без истории:10393
  Кривая без истории:10394
  Кривая без истории:10395
  Кривая без истории:10396
  Кривая без истории:10397
  Кривая без истории:10398
  Кривая без истории:10399
  Кривая без истории:10400
  Кривая без истории:10401
  Кривая без истории:10402
  Кривая без истории:10403
  Кривая без истории:10404
  Кривая без истории:10405
  Кривая без истории:10406
  Кривая без истории:10407
  Кривая без истории:10408
  Кривая без истории:10409
  Кривая без истории:10410
  Кривая без истории:10411
  Кривая без истории:10412
  Кривая без истории:10413
  Кривая без истории:10414
  Кривая без истории:10415
  Кривая без истории:10416
  Кривая без истории:10417
  Кривая без истории:10418
  Кривая без истории:10419
  Кривая без истории:10420
  Кривая без истории:10421
  Кривая без истории:10422
  Кривая без истории:10423
  Кривая без истории:10424
  Кривая без истории:10425
  Кривая без истории:10426
  Кривая без истории:10427
  Кривая без истории:10428
  Кривая без истории:10429
  Кривая без истории:10430
  Кривая без истории:10431
  Кривая без истории:10432
  Кривая без истории:10433
  Кривая без истории:10434
  Кривая без истории:10435
  Кривая без истории:10436
  Кривая без истории:10437
  Кривая без истории:10438
  Кривая без истории:10439
  Кривая без истории:10440
  Кривая без истории:10441
  Кривая без истории:10442
  Кривая без истории:10443
  Кривая без истории:10444
  Кривая без истории:10445
  Кривая без истории:10446
  Кривая без истории:10447
  Кривая без истории:10448
  Кривая без истории:10449
  Кривая без истории:10450
  Кривая без истории:10451
  Кривая без истории:10452
  Кривая без истории:10453
  Кривая без истории:10454
  Кривая без истории:10455
  Кривая без истории:10456
  Кривая без истории:10457
  Кривая без истории:10458
  Кривая без истории:10459
  Кривая без истории:10460
  Кривая без истории:10461
  Кривая без истории:10462
  Кривая без истории:10463
  Кривая без истории:10464
  Кривая без истории:10465
  Кривая без истории:10466
  Кривая без истории:10467
  Кривая без истории:10468
  Кривая без истории:10469
  Кривая без истории:10470
  Кривая без истории:10471
  Кривая без истории:10472
  Кривая без истории:10473
  Кривая без истории:10474
  Кривая без истории:10475
  Кривая без истории:10476
  Кривая без истории:10477
  Кривая без истории:10478
  Кривая без истории:10479
  Кривая без истории:10480
  Кривая без истории:10481
  Кривая без истории:10482
  Кривая без истории:10483
  Кривая без истории:10484
  Кривая без истории:10485
  Кривая без истории:10486
  Кривая без истории:10487
  Кривая без истории:10488
  Кривая без истории:10489
  Кривая без истории:10490
  Кривая без истории:10491
  Кривая без истории:10492
  Кривая без истории:10493
  Кривая без истории:10494
  Кривая без истории:10495
  Кривая без истории:10496
  Кривая без истории:10497
  Кривая без истории:10498
  Кривая без истории:10499
  Кривая без истории:10500
  Кривая без истории:10501
  Кривая без истории:10502
  Кривая без истории:10503
  Кривая без истории:10504
  Кривая без истории:10505
  Кривая без истории:10506
  Кривая без истории:10507
  Кривая без истории:10508
  Кривая без истории:10509
  Кривая без истории:10510
  Кривая без истории:10511
  Кривая без истории:10512
  Кривая без истории:10513
  Кривая без истории:10514
  Кривая без истории:10515
  Кривая без истории:10516
  Кривая без истории:10517
  Кривая без истории:10518
  Кривая без истории:10519
  Кривая без истории:10520
  Кривая без истории:10521
  Кривая без истории:10522
  Кривая без истории:10523
  Кривая без истории:10524
  Кривая без истории:10525
  Кривая без истории:10526
  Кривая без истории:10527
  Кривая без истории:10528
  Кривая без истории:10529
  Кривая без истории:10530
  Кривая без истории:10531
  Кривая без истории:10532
  Кривая без истории:10533
  Кривая без истории:10534
  Кривая без истории:10535
  Кривая без истории:10536
  Кривая без истории:10537
  Кривая без истории:10538
  Кривая без истории:10539
  Кривая без истории:10540
  Кривая без истории:10541
  Кривая без истории:10542
  Кривая без истории:10543
  Кривая без истории:10544
  Кривая без истории:10545
  Кривая без истории:10546
  Кривая без истории:10547
  Кривая без истории:10548
  Кривая без истории:10549
  Кривая без истории:10550
  Кривая без истории:10551
  Кривая без истории:10552
  Кривая без истории:10553
  Кривая без истории:10554
  Кривая без истории:10555
  Кривая без истории:10556
  Кривая без истории:10557
  Кривая без истории:10558
  Кривая без истории:10559
  Кривая без истории:10560
  Кривая без истории:10561
  Кривая без истории:10562
  Кривая без истории:10563
  Кривая без истории:10564
  Кривая без истории:10565
  Кривая без истории:10566
  Кривая без истории:10567
  Кривая без истории:10568
  Кривая без истории:10569
  Кривая без истории:10570
  Кривая без истории:10571
  Кривая без истории:10572
  Кривая без истории:10573
  Кривая без истории:10574
  Кривая без истории:10575
  Кривая без истории:10576
  Кривая без истории:10577
  Кривая без истории:10578
  Кривая без истории:10579
  Кривая без истории:10580
  Кривая без истории:10581
  Кривая без истории:10582
  Кривая без истории:10583
  Кривая без истории:10584
  Кривая без истории:10585
  Кривая без истории:10586
  Кривая без истории:10587
  Кривая без истории:10588
  Кривая без истории:10589
  Кривая без истории:10590
  Кривая без истории:10591
  Кривая без истории:10592
  Кривая без истории:10593
  Кривая без истории:10594
  Кривая без истории:10595
  Кривая без истории:10596
  Кривая без истории:10597
  Кривая без истории:10598
  Кривая без истории:10599
  Кривая без истории:10600
  Кривая без истории:10601
  Кривая без истории:10602
  Кривая без истории:10603
  Кривая без истории:10604
  Кривая без истории:10605
  Кривая без истории:10606
  Кривая без истории:10607
  Кривая без истории:10608
  Кривая без истории:10609
  Кривая без истории:10610
  Кривая без истории:10611
  Кривая без истории:10612
  Кривая без истории:10613
  Кривая без истории:10614
  Кривая без истории:10615
  Кривая без истории:10616
  Кривая без истории:10617
  Кривая без истории:10618
  Кривая без истории:10619
  Кривая без истории:10620
  Кривая без истории:10621
  Кривая без истории:10622
  Кривая без истории:10623
  Кривая без истории:10624
  Кривая без истории:10625
  Кривая без истории:10626
  Кривая без истории:10627
  Кривая без истории:10628
  Кривая без истории:10629
  Кривая без истории:10630
  Кривая без истории:10631
  Кривая без истории:10632
  Кривая без истории:10633
  Кривая без истории:10634
  Кривая без истории:10635
  Кривая без истории:10636
  Кривая без истории:10637
  Кривая без истории:10638
  Кривая без истории:10639
  Кривая без истории:10640
  Кривая без истории:10641
  Кривая без истории:10642
  Кривая без истории:10643
  Кривая без истории:10644
  Кривая без истории:10645
  Кривая без истории:10646
  Кривая без истории:10647
  Кривая без истории:10648
  Кривая без истории:10649
  Кривая без истории:10650
  Кривая без истории:10651
  Кривая без истории:10652
  Кривая без истории:10653
  Кривая без истории:10654
  Кривая без истории:10655
  Кривая без истории:10656
  Кривая без истории:10657
  Кривая без истории:10658
  Кривая без истории:10659
  Кривая без истории:10660
  Кривая без истории:10661
  Кривая без истории:10662
  Кривая без истории:10663
  Кривая без истории:10664
  Кривая без истории:10665
  Кривая без истории:10666
  Кривая без истории:10667
  Кривая без истории:10668
  Кривая без истории:10669
  Кривая без истории:10670
  Кривая без истории:10671
  Кривая без истории:10672
  Кривая без истории:10673
  Кривая без истории:10674
  Кривая без истории:10675
  Кривая без истории:10676
  Кривая без истории:10677
  Кривая без истории:10678
  Кривая без истории:10679
  Кривая без истории:10680
  Кривая без истории:10681
  Кривая без истории:10682
  Кривая без истории:10683
  Кривая без истории:10684
  Кривая без истории:10685
  Кривая без истории:10686
  Кривая без истории:10687
  Кривая без истории:10688
  Кривая без истории:10689
  Кривая без истории:10690
  Кривая без истории:10691
  Кривая без истории:10692
  Кривая без истории:10693
  Кривая без истории:10694
  Кривая без истории:10695
  Кривая без истории:10696
  Кривая без истории:10697
  Кривая без истории:10698
  Кривая без истории:10699
  Кривая без истории:10700
  Кривая без истории:10701
  Кривая без истории:10702
  Кривая без истории:10703
  Кривая без истории:10704
  Кривая без истории:10705
  Кривая без истории:10706
  Кривая без истории:10707
  Кривая без истории:10708
  Кривая без истории:10709
  Кривая без истории:10710
  Кривая без истории:10711
  Кривая без истории:10712
  Кривая без истории:10713
  Кривая без истории:10714
  Кривая без истории:10715
  Кривая без истории:10716
  Кривая без истории:10717
  Кривая без истории:10718
  Кривая без истории:10719
  Кривая без истории:10720
  Кривая без истории:10721
  Кривая без истории:10722
  Кривая без истории:10723
  Кривая без истории:10724
  Кривая без истории:10725
  Кривая без истории:10726
  Кривая без истории:10727
  Кривая без истории:10728
  Кривая без истории:10729
  Кривая без истории:10730
  Кривая без истории:10731
  Кривая без истории:10732
  Кривая без истории:10733
  Кривая без истории:10734
  Кривая без истории:10735
  Кривая без истории:10736
  Кривая без истории:10737
  Кривая без истории:10738
  Кривая без истории:10739
  Кривая без истории:10740
  Кривая без истории:10741
  Кривая без истории:10742
  Кривая без истории:10743
  Кривая без истории:10744
  Кривая без истории:10745
  Кривая без истории:10746
  Кривая без истории:10747
  Кривая без истории:10748
  Кривая без истории:10749
  Кривая без истории:10750
  Кривая без истории:10751
  Кривая без истории:10752
  Кривая без истории:10753
  Кривая без истории:10754
  Кривая без истории:10755
  Кривая без истории:10756
  Кривая без истории:10757
  Кривая без истории:10758
  Кривая без истории:10759
  Кривая без истории:10760
  Кривая без истории:10761
  Кривая без истории:10762
  Кривая без истории:10763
